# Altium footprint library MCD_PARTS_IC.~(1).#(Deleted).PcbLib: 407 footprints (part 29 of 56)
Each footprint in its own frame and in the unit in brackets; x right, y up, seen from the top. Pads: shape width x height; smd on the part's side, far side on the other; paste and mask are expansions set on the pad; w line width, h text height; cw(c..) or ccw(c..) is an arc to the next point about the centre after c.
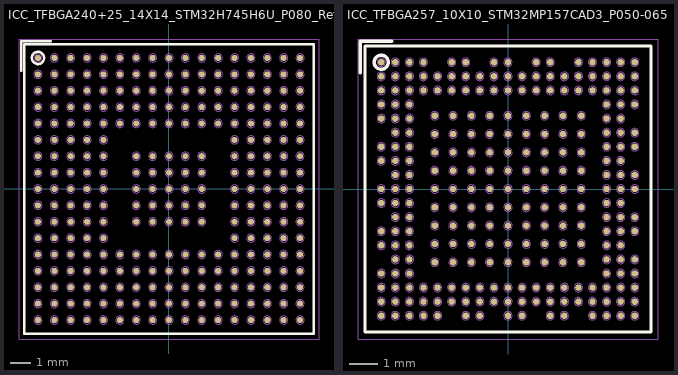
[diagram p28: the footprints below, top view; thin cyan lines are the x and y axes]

## ICC_TFBGA240+25_14X14_STM32H745H6U_P080_Ref2 [mm]
height 1.1
pads (265):
  round 0.3 smd mask+0.05: .U15(4.8,-6.4) A1(-6.4,6.4) A2(-5.6,6.4) A3(-4.8,6.4) A4(-4,6.4) A5(-3.2,6.4) A6(-2.4,6.4) A7(-1.6,6.4) A8(-0.8,6.4) A9(0,6.4) A10(0.8,6.4) A11(1.6,6.4) A12(2.4,6.4) A13(3.2,6.4) A14(4,6.4) A15(4.8,6.4) A16(5.6,6.4) A17(6.4,6.4) B1(-6.4,5.6) B2(-5.6,5.6) B3(-4.8,5.6) B4(-4,5.6) B5(-3.2,5.6) B6(-2.4,5.6) B7(-1.6,5.6) B8(-0.8,5.6) B9(0,5.6) B10(0.8,5.6) B11(1.6,5.6) B12(2.4,5.6) B13(3.2,5.6) B14(4,5.6) B15(4.8,5.6) B16(5.6,5.6) B17(6.4,5.6) C1(-6.4,4.8) C2(-5.6,4.8) C3(-4.8,4.8) C4(-4,4.8) C5(-3.2,4.8) C6(-2.4,4.8) C7(-1.6,4.8) C8(-0.8,4.8) C9(0,4.8) C10(0.8,4.8) C11(1.6,4.8) C12(2.4,4.8) C13(3.2,4.8) C14(4,4.8) C15(4.8,4.8) C16(5.6,4.8) C17(6.4,4.8) D1(-6.4,4) D2(-5.6,4) D3(-4.8,4) D4(-4,4) D5(-3.2,4) D6(-2.4,4) D7(-1.6,4) D8(-0.8,4) D9(0,4) D10(0.8,4) D11(1.6,4) D12(2.4,4) D13(3.2,4) D14(4,4) D15(4.8,4) D16(5.6,4) D17(6.4,4) E1(-6.4,3.2) E2(-5.6,3.2) E3(-4.8,3.2) E4(-4,3.2) E5(-3.2,3.2) E6(-2.4,3.2) E7(-1.6,3.2) E8(-0.8,3.2) E9(0,3.2) E10(0.8,3.2) E11(1.6,3.2) E12(2.4,3.2) E13(3.2,3.2) E14(4,3.2) E15(4.8,3.2) E16(5.6,3.2) E17(6.4,3.2) F1(-6.4,2.4) F2(-5.6,2.4) F3(-4.8,2.4) F4(-4,2.4) F5(-3.2,2.4) F13(3.2,2.4) F14(4,2.4) F15(4.8,2.4) F16(5.6,2.4) F17(6.4,2.4) G1(-6.4,1.6) G2(-5.6,1.6) G3(-4.8,1.6) G4(-4,1.6) G5(-3.2,1.6) G7(-1.6,1.6) G8(-0.8,1.6) G9(0,1.6) G10(0.8,1.6) G11(1.6,1.6) G13(3.2,1.6) G14(4,1.6) G15(4.8,1.6) G16(5.6,1.6) G17(6.4,1.6) H1(-6.4,0.8) H2(-5.6,0.8) H3(-4.8,0.8) H4(-4,0.8) H5(-3.2,0.8) H7(-1.6,0.8) H8(-0.8,0.8) H9(0,0.8) H10(0.8,0.8) H11(1.6,0.8) H13(3.2,0.8) H14(4,0.8) H15(4.8,0.8) H16(5.6,0.8) H17(6.4,0.8) J1(-6.4,0) J2(-5.6,0) J3(-4.8,0) J4(-4,0) J5(-3.2,0) J7(-1.6,0) J8(-0.8,0) J9(0,0) J10(0.8,0) J11(1.6,0) J13(3.2,0) J14(4,0) J15(4.8,0) J16(5.6,0) J17(6.4,0) K1(-6.4,-0.8) K2(-5.6,-0.8) K3(-4.8,-0.8) K4(-4,-0.8) K5(-3.2,-0.8) K7(-1.6,-0.8) K8(-0.8,-0.8) K9(0,-0.8) K10(0.8,-0.8) K11(1.6,-0.8) K13(3.2,-0.8) K14(4,-0.8) K15(4.8,-0.8) K16(5.6,-0.8) K17(6.4,-0.8) L1(-6.4,-1.6) L2(-5.6,-1.6) L3(-4.8,-1.6) L4(-4,-1.6) L5(-3.2,-1.6) L7(-1.6,-1.6) L8(-0.8,-1.6) L9(0,-1.6) L10(0.8,-1.6) L11(1.6,-1.6) L13(3.2,-1.6) L14(4,-1.6) L15(4.8,-1.6) L16(5.6,-1.6) L17(6.4,-1.6) M1(-6.4,-2.4) M2(-5.6,-2.4) M3(-4.8,-2.4) M4(-4,-2.4) M5(-3.2,-2.4) M13(3.2,-2.4) M14(4,-2.4) M15(4.8,-2.4) M16(5.6,-2.4) M17(6.4,-2.4) N1(-6.4,-3.2) N2(-5.6,-3.2) N3(-4.8,-3.2) N4(-4,-3.2) N5(-3.2,-3.2) N6(-2.4,-3.2) N7(-1.6,-3.2) N8(-0.8,-3.2) N9(0,-3.2) N10(0.8,-3.2) N11(1.6,-3.2) N12(2.4,-3.2) N13(3.2,-3.2) N14(4,-3.2) N15(4.8,-3.2) N16(5.6,-3.2) N17(6.4,-3.2) P1(-6.4,-4) P2(-5.6,-4) P3(-4.8,-4) P4(-4,-4) P5(-3.2,-4) P6(-2.4,-4) P7(-1.6,-4) P8(-0.8,-4) P9(0,-4) P10(0.8,-4) P11(1.6,-4) P12(2.4,-4) P13(3.2,-4) P14(4,-4) P15(4.8,-4) P16(5.6,-4) P17(6.4,-4) R1(-6.4,-4.8) R2(-5.6,-4.8) R3(-4.8,-4.8) R4(-4,-4.8) R5(-3.2,-4.8) R6(-2.4,-4.8) R7(-1.6,-4.8) R8(-0.8,-4.8) R9(0,-4.8) R10(0.8,-4.8) R11(1.6,-4.8) R12(2.4,-4.8) R13(3.2,-4.8) R14(4,-4.8) R15(4.8,-4.8) R16(5.6,-4.8) R17(6.4,-4.8) T1(-6.4,-5.6) T2(-5.6,-5.6) T3(-4.8,-5.6) T4(-4,-5.6) T5(-3.2,-5.6) T6(-2.4,-5.6) T7(-1.6,-5.6) T8(-0.8,-5.6) T9(0,-5.6) T10(0.8,-5.6) T11(1.6,-5.6) T12(2.4,-5.6) T13(3.2,-5.6) T14(4,-5.6) T15(4.8,-5.6) T16(5.6,-5.6) T17(6.4,-5.6) U1(-6.4,-6.4) U2(-5.6,-6.4) U3(-4.8,-6.4) U4(-4,-6.4) U5(-3.2,-6.4) U6(-2.4,-6.4) U7(-1.6,-6.4) U8(-0.8,-6.4) U9(0,-6.4) U10(0.8,-6.4) U11(1.6,-6.4) U12(2.4,-6.4) U13(3.2,-6.4) U14(4,-6.4) U16(5.6,-6.4) U17(6.4,-6.4)
Top Overlay:
  circle w0.12: c-6.4,6.4 r0.3
  lines w0.12: -7.225,5.775 -7.225,7.225 -5.775,7.225 ; -7.075,-7.075 -7.075,7.075 7.075,7.075 7.075,-7.075 -7.075,-7.075
M14-Top Assembly:
  drawing of 269 lines, arcs and shapes, not listed
  text "A1" at -6.65,6.225 h0.4
  text "'.Designator'" at -2,-0.5 h0.75
M16-Top Courtyard:
  lines w0.01: -7.325,-7.325 -7.325,7.325 7.325,7.325 7.325,-7.325 -7.325,-7.325
3D body: height 1.11, standoff 1.1, extent -6.698,6.101 -6.1,6.699
3D body: height 0.36, standoff -0.04, extent 4.601,-4.997 5,-4.603
3D body: height 0.36, standoff -0.04, extent 3.801,-4.997 4.2,-4.603
3D body: height 0.36, standoff -0.04, extent 3.001,-4.997 3.4,-4.603
3D body: height 0.36, standoff -0.04, extent 2.201,-4.997 2.6,-4.603
3D body: height 0.36, standoff -0.04, extent 1.401,-4.997 1.8,-4.603
3D body: height 0.36, standoff -0.04, extent -2.599,-4.997 -2.2,-4.603
3D body: height 0.36, standoff -0.04, extent -1.799,-4.997 -1.4,-4.603
3D body: height 0.36, standoff -0.04, extent -0.999,-4.997 -0.6,-4.603
3D body: height 0.36, standoff -0.04, extent -0.199,-4.997 0.2,-4.603
3D body: height 0.36, standoff -0.04, extent 0.601,-4.997 1,-4.603
3D body: height 0.36, standoff -0.04, extent -6.599,-4.997 -6.2,-4.603
3D body: height 0.36, standoff -0.04, extent -5.799,-4.997 -5.4,-4.603
3D body: height 0.36, standoff -0.04, extent -4.999,-4.997 -4.6,-4.603
3D body: height 0.36, standoff -0.04, extent -4.199,-4.997 -3.8,-4.603
3D body: height 0.36, standoff -0.04, extent -3.399,-4.997 -3,-4.603
3D body: height 0.36, standoff -0.04, extent 4.601,-4.197 5,-3.803
3D body: height 0.36, standoff -0.04, extent 3.801,-4.197 4.2,-3.803
3D body: height 0.36, standoff -0.04, extent 3.001,-4.197 3.4,-3.803
3D body: height 0.36, standoff -0.04, extent 2.201,-4.197 2.6,-3.803
3D body: height 0.36, standoff -0.04, extent 1.401,-4.197 1.8,-3.803
3D body: height 0.36, standoff -0.04, extent -2.599,-4.197 -2.2,-3.803
3D body: height 0.36, standoff -0.04, extent -1.799,-4.197 -1.4,-3.803
3D body: height 0.36, standoff -0.04, extent -0.999,-4.197 -0.6,-3.803
3D body: height 0.36, standoff -0.04, extent -0.199,-4.197 0.2,-3.803
3D body: height 0.36, standoff -0.04, extent 0.601,-4.197 1,-3.803
3D body: height 0.36, standoff -0.04, extent -6.599,-4.197 -6.2,-3.803
3D body: height 0.36, standoff -0.04, extent -5.799,-4.197 -5.4,-3.803
3D body: height 0.36, standoff -0.04, extent -4.999,-4.197 -4.6,-3.803
3D body: height 0.36, standoff -0.04, extent -4.199,-4.197 -3.8,-3.803
3D body: height 0.36, standoff -0.04, extent -3.399,-4.197 -3,-3.803
3D body: height 0.36, standoff -0.04, extent 4.601,-3.397 5,-3.003
3D body: height 0.36, standoff -0.04, extent 3.801,-3.397 4.2,-3.003
3D body: height 0.36, standoff -0.04, extent 3.001,-3.397 3.4,-3.003
3D body: height 0.36, standoff -0.04, extent 2.201,-3.397 2.6,-3.003
3D body: height 0.36, standoff -0.04, extent 1.401,-3.397 1.8,-3.003
3D body: height 0.36, standoff -0.04, extent -2.599,-3.397 -2.2,-3.003
3D body: height 0.36, standoff -0.04, extent -1.799,-3.397 -1.4,-3.003
3D body: height 0.36, standoff -0.04, extent -0.999,-3.397 -0.6,-3.003
3D body: height 0.36, standoff -0.04, extent -0.199,-3.397 0.2,-3.003
3D body: height 0.36, standoff -0.04, extent 0.601,-3.397 1,-3.003
3D body: height 0.36, standoff -0.04, extent -6.599,-3.397 -6.2,-3.003
3D body: height 0.36, standoff -0.04, extent -5.799,-3.397 -5.4,-3.003
3D body: height 0.36, standoff -0.04, extent -4.999,-3.397 -4.6,-3.003
3D body: height 0.36, standoff -0.04, extent -4.199,-3.397 -3.8,-3.003
3D body: height 0.36, standoff -0.04, extent -3.399,-3.397 -3,-3.003
3D body: height 0.36, standoff -0.04, extent 4.601,-2.597 5,-2.203
3D body: height 0.36, standoff -0.04, extent 3.801,-2.597 4.2,-2.203
3D body: height 0.36, standoff -0.04, extent 3.001,-2.597 3.4,-2.203
3D body: height 0.36, standoff -0.04, extent -6.599,-2.597 -6.2,-2.203
3D body: height 0.36, standoff -0.04, extent -5.799,-2.597 -5.4,-2.203
3D body: height 0.36, standoff -0.04, extent -4.999,-2.597 -4.6,-2.203
3D body: height 0.36, standoff -0.04, extent -4.199,-2.597 -3.8,-2.203
3D body: height 0.36, standoff -0.04, extent -3.399,-2.597 -3,-2.203
3D body: height 0.36, standoff -0.04, extent 4.601,-1.797 5,-1.403
3D body: height 0.36, standoff -0.04, extent 3.801,-1.797 4.2,-1.403
3D body: height 0.36, standoff -0.04, extent 3.001,-1.797 3.4,-1.403
3D body: height 0.36, standoff -0.04, extent 1.401,-1.797 1.8,-1.403
3D body: height 0.36, standoff -0.04, extent -1.799,-1.797 -1.4,-1.403
3D body: height 0.36, standoff -0.04, extent -0.999,-1.797 -0.6,-1.403
3D body: height 0.36, standoff -0.04, extent -0.199,-1.797 0.2,-1.403
3D body: height 0.36, standoff -0.04, extent 0.601,-1.797 1,-1.403
3D body: height 0.36, standoff -0.04, extent -6.599,-1.797 -6.2,-1.403
3D body: height 0.36, standoff -0.04, extent -5.799,-1.797 -5.4,-1.403
3D body: height 0.36, standoff -0.04, extent -4.999,-1.797 -4.6,-1.403
3D body: height 0.36, standoff -0.04, extent -4.199,-1.797 -3.8,-1.403
3D body: height 0.36, standoff -0.04, extent -3.399,-1.797 -3,-1.403
3D body: height 0.36, standoff -0.04, extent 4.601,-0.997 5,-0.603
3D body: height 0.36, standoff -0.04, extent 3.801,-0.997 4.2,-0.603
3D body: height 0.36, standoff -0.04, extent 3.001,-0.997 3.4,-0.603
3D body: height 0.36, standoff -0.04, extent 1.401,-0.997 1.8,-0.603
3D body: height 0.36, standoff -0.04, extent -1.799,-0.997 -1.4,-0.603
3D body: height 0.36, standoff -0.04, extent -0.999,-0.997 -0.6,-0.603
3D body: height 0.36, standoff -0.04, extent -0.199,-0.997 0.2,-0.603
3D body: height 0.36, standoff -0.04, extent 0.601,-0.997 1,-0.603
3D body: height 0.36, standoff -0.04, extent -6.599,-0.997 -6.2,-0.603
3D body: height 0.36, standoff -0.04, extent -5.799,-0.997 -5.4,-0.603
3D body: height 0.36, standoff -0.04, extent -4.999,-0.997 -4.6,-0.603
3D body: height 0.36, standoff -0.04, extent -4.199,-0.997 -3.8,-0.603
3D body: height 0.36, standoff -0.04, extent -3.399,-0.997 -3,-0.603
3D body: height 0.36, standoff -0.04, extent 4.601,-0.197 5,0.197
3D body: height 0.36, standoff -0.04, extent 3.801,-0.197 4.2,0.197
3D body: height 0.36, standoff -0.04, extent 3.001,-0.197 3.4,0.197
3D body: height 0.36, standoff -0.04, extent 1.401,-0.197 1.8,0.197
3D body: height 0.36, standoff -0.04, extent -1.799,-0.197 -1.4,0.197
3D body: height 0.36, standoff -0.04, extent -0.999,-0.197 -0.6,0.197
3D body: height 0.36, standoff -0.04, extent -0.199,-0.197 0.2,0.197
3D body: height 0.36, standoff -0.04, extent 0.601,-0.197 1,0.197
3D body: height 0.36, standoff -0.04, extent -6.599,-0.197 -6.2,0.197
3D body: height 0.36, standoff -0.04, extent -5.799,-0.197 -5.4,0.197
3D body: height 0.36, standoff -0.04, extent -4.999,-0.197 -4.6,0.197
3D body: height 0.36, standoff -0.04, extent -4.199,-0.197 -3.8,0.197
3D body: height 0.36, standoff -0.04, extent -3.399,-0.197 -3,0.197
3D body: height 0.36, standoff -0.04, extent 4.601,0.603 5,0.997
3D body: height 0.36, standoff -0.04, extent 3.801,0.603 4.2,0.997
3D body: height 0.36, standoff -0.04, extent 3.001,0.603 3.4,0.997
3D body: height 0.36, standoff -0.04, extent 1.401,0.603 1.8,0.997
3D body: height 0.36, standoff -0.04, extent -1.799,0.603 -1.4,0.997
3D body: height 0.36, standoff -0.04, extent -0.999,0.603 -0.6,0.997
3D body: height 0.36, standoff -0.04, extent -0.199,0.603 0.2,0.997
3D body: height 0.36, standoff -0.04, extent 0.601,0.603 1,0.997
3D body: height 0.36, standoff -0.04, extent -6.599,0.603 -6.2,0.997
3D body: height 0.36, standoff -0.04, extent -5.799,0.603 -5.4,0.997
3D body: height 0.36, standoff -0.04, extent -4.999,0.603 -4.6,0.997
3D body: height 0.36, standoff -0.04, extent -4.199,0.603 -3.8,0.997
3D body: height 0.36, standoff -0.04, extent -3.399,0.603 -3,0.997
3D body: height 0.36, standoff -0.04, extent 4.601,1.403 5,1.797
3D body: height 0.36, standoff -0.04, extent 3.801,1.403 4.2,1.797
3D body: height 0.36, standoff -0.04, extent 3.001,1.403 3.4,1.797
3D body: height 0.36, standoff -0.04, extent 1.401,1.403 1.8,1.797
3D body: height 0.36, standoff -0.04, extent -1.799,1.403 -1.4,1.797
3D body: height 0.36, standoff -0.04, extent -0.999,1.403 -0.6,1.797
3D body: height 0.36, standoff -0.04, extent -0.199,1.403 0.2,1.797
3D body: height 0.36, standoff -0.04, extent 0.601,1.403 1,1.797
3D body: height 0.36, standoff -0.04, extent -6.599,1.403 -6.2,1.797
3D body: height 0.36, standoff -0.04, extent -5.799,1.403 -5.4,1.797
3D body: height 0.36, standoff -0.04, extent -4.999,1.403 -4.6,1.797
3D body: height 0.36, standoff -0.04, extent -4.199,1.403 -3.8,1.797
3D body: height 0.36, standoff -0.04, extent -3.399,1.403 -3,1.797
3D body: height 0.36, standoff -0.04, extent 4.601,2.203 5,2.597
3D body: height 0.36, standoff -0.04, extent 3.801,2.203 4.2,2.597
3D body: height 0.36, standoff -0.04, extent 3.001,2.203 3.4,2.597
3D body: height 0.36, standoff -0.04, extent -6.599,2.203 -6.2,2.597
3D body: height 0.36, standoff -0.04, extent -5.799,2.203 -5.4,2.597
3D body: height 0.36, standoff -0.04, extent -4.999,2.203 -4.6,2.597
3D body: height 0.36, standoff -0.04, extent -4.199,2.203 -3.8,2.597
3D body: height 0.36, standoff -0.04, extent -3.399,2.203 -3,2.597
3D body: height 0.36, standoff -0.04, extent 4.601,3.003 5,3.397
3D body: height 0.36, standoff -0.04, extent 3.801,3.003 4.2,3.397
3D body: height 0.36, standoff -0.04, extent 3.001,3.003 3.4,3.397
3D body: height 0.36, standoff -0.04, extent 2.201,3.003 2.6,3.397
3D body: height 0.36, standoff -0.04, extent 1.401,3.003 1.8,3.397
3D body: height 0.36, standoff -0.04, extent -2.599,3.003 -2.2,3.397
3D body: height 0.36, standoff -0.04, extent -1.799,3.003 -1.4,3.397
3D body: height 0.36, standoff -0.04, extent -0.999,3.003 -0.6,3.397
3D body: height 0.36, standoff -0.04, extent -0.199,3.003 0.2,3.397
3D body: height 0.36, standoff -0.04, extent 0.601,3.003 1,3.397
3D body: height 0.36, standoff -0.04, extent -6.599,3.003 -6.2,3.397
3D body: height 0.36, standoff -0.04, extent -5.799,3.003 -5.4,3.397
3D body: height 0.36, standoff -0.04, extent -4.999,3.003 -4.6,3.397
3D body: height 0.36, standoff -0.04, extent -4.199,3.003 -3.8,3.397
3D body: height 0.36, standoff -0.04, extent -3.399,3.003 -3,3.397
3D body: height 0.36, standoff -0.04, extent 4.601,3.803 5,4.197
3D body: height 0.36, standoff -0.04, extent 3.801,3.803 4.2,4.197
3D body: height 0.36, standoff -0.04, extent 3.001,3.803 3.4,4.197
3D body: height 0.36, standoff -0.04, extent 2.201,3.803 2.6,4.197
3D body: height 0.36, standoff -0.04, extent 1.401,3.803 1.8,4.197
3D body: height 0.36, standoff -0.04, extent -2.599,3.803 -2.2,4.197
3D body: height 0.36, standoff -0.04, extent -1.799,3.803 -1.4,4.197
3D body: height 0.36, standoff -0.04, extent -0.999,3.803 -0.6,4.197
3D body: height 0.36, standoff -0.04, extent -0.199,3.803 0.2,4.197
3D body: height 0.36, standoff -0.04, extent 0.601,3.803 1,4.197
3D body: height 0.36, standoff -0.04, extent -6.599,3.803 -6.2,4.197
3D body: height 0.36, standoff -0.04, extent -5.799,3.803 -5.4,4.197
3D body: height 0.36, standoff -0.04, extent -4.999,3.803 -4.6,4.197
3D body: height 0.36, standoff -0.04, extent -4.199,3.803 -3.8,4.197
3D body: height 0.36, standoff -0.04, extent -3.399,3.803 -3,4.197
3D body: height 0.36, standoff -0.04, extent 4.601,4.603 5,4.997
3D body: height 0.36, standoff -0.04, extent 3.801,4.603 4.2,4.997
3D body: height 0.36, standoff -0.04, extent 3.001,4.603 3.4,4.997
3D body: height 0.36, standoff -0.04, extent 2.201,4.603 2.6,4.997
3D body: height 0.36, standoff -0.04, extent 1.401,4.603 1.8,4.997
3D body: height 0.36, standoff -0.04, extent -2.599,4.603 -2.2,4.997
3D body: height 0.36, standoff -0.04, extent -1.799,4.603 -1.4,4.997
3D body: height 0.36, standoff -0.04, extent -0.999,4.603 -0.6,4.997
3D body: height 0.36, standoff -0.04, extent -0.199,4.603 0.2,4.997
3D body: height 0.36, standoff -0.04, extent 0.601,4.603 1,4.997
3D body: height 0.36, standoff -0.04, extent -6.599,4.603 -6.2,4.997
3D body: height 0.36, standoff -0.04, extent -5.799,4.603 -5.4,4.997
3D body: height 0.36, standoff -0.04, extent -4.999,4.603 -4.6,4.997
3D body: height 0.36, standoff -0.04, extent -4.199,4.603 -3.8,4.997
3D body: height 0.36, standoff -0.04, extent -3.399,4.603 -3,4.997
3D body: height 0.36, standoff -0.04, extent 4.601,5.403 5,5.797
3D body: height 0.36, standoff -0.04, extent 3.801,5.403 4.2,5.797
3D body: height 0.36, standoff -0.04, extent 3.001,5.403 3.4,5.797
3D body: height 0.36, standoff -0.04, extent 2.201,5.403 2.6,5.797
3D body: height 0.36, standoff -0.04, extent 1.401,5.403 1.8,5.797
3D body: height 0.36, standoff -0.04, extent -2.599,5.403 -2.2,5.797
3D body: height 0.36, standoff -0.04, extent -1.799,5.403 -1.4,5.797
3D body: height 0.36, standoff -0.04, extent -0.999,5.403 -0.6,5.797
3D body: height 0.36, standoff -0.04, extent -0.199,5.403 0.2,5.797
3D body: height 0.36, standoff -0.04, extent 0.601,5.403 1,5.797
3D body: height 0.36, standoff -0.04, extent -6.599,5.403 -6.2,5.797
3D body: height 0.36, standoff -0.04, extent -5.799,5.403 -5.4,5.797
3D body: height 0.36, standoff -0.04, extent -4.999,5.403 -4.6,5.797
3D body: height 0.36, standoff -0.04, extent -4.199,5.403 -3.8,5.797
3D body: height 0.36, standoff -0.04, extent -3.399,5.403 -3,5.797
3D body: height 0.36, standoff -0.04, extent -3.399,6.203 -3,6.597
3D body: height 0.36, standoff -0.04, extent -4.199,6.203 -3.8,6.597
3D body: height 0.36, standoff -0.04, extent -4.999,6.203 -4.6,6.597
3D body: height 0.36, standoff -0.04, extent -5.799,6.203 -5.4,6.597
3D body: height 0.36, standoff -0.04, extent -6.599,6.203 -6.2,6.597
3D body: height 0.36, standoff -0.04, extent 0.601,6.203 1,6.597
3D body: height 0.36, standoff -0.04, extent -0.199,6.203 0.2,6.597
3D body: height 0.36, standoff -0.04, extent -0.999,6.203 -0.6,6.597
3D body: height 0.36, standoff -0.04, extent -1.799,6.203 -1.4,6.597
3D body: height 0.36, standoff -0.04, extent -2.599,6.203 -2.2,6.597
3D body: height 0.36, standoff -0.04, extent 1.401,6.203 1.8,6.597
3D body: height 0.36, standoff -0.04, extent 2.201,6.203 2.6,6.597
3D body: height 0.36, standoff -0.04, extent 3.001,6.203 3.4,6.597
3D body: height 0.36, standoff -0.04, extent 3.801,6.203 4.2,6.597
3D body: height 1.1, standoff 0.3, extent -7.075,-7.075 7.075,7.075
3D body: height 0.36, standoff -0.04, extent 4.601,6.203 5,6.597
3D body: height 0.36, standoff -0.04, extent 6.201,6.203 6.6,6.597
3D body: height 0.36, standoff -0.04, extent 5.401,6.203 5.8,6.597
3D body: height 0.36, standoff -0.04, extent 5.401,5.403 5.8,5.797
3D body: height 0.36, standoff -0.04, extent 6.201,5.403 6.6,5.797
3D body: height 0.36, standoff -0.04, extent 5.401,4.603 5.8,4.997
3D body: height 0.36, standoff -0.04, extent 6.201,4.603 6.6,4.997
3D body: height 0.36, standoff -0.04, extent 5.401,3.803 5.8,4.197
3D body: height 0.36, standoff -0.04, extent 6.201,3.803 6.6,4.197
3D body: height 0.36, standoff -0.04, extent 5.401,3.003 5.8,3.397
3D body: height 0.36, standoff -0.04, extent 6.201,3.003 6.6,3.397
3D body: height 0.36, standoff -0.04, extent 5.401,2.203 5.8,2.597
3D body: height 0.36, standoff -0.04, extent 6.201,2.203 6.6,2.597
3D body: height 0.36, standoff -0.04, extent 5.401,1.403 5.8,1.797
3D body: height 0.36, standoff -0.04, extent 6.201,1.403 6.6,1.797
3D body: height 0.36, standoff -0.04, extent 5.401,0.603 5.8,0.997
3D body: height 0.36, standoff -0.04, extent 6.201,0.603 6.6,0.997
3D body: height 0.36, standoff -0.04, extent 5.401,-0.197 5.8,0.197
3D body: height 0.36, standoff -0.04, extent 6.201,-0.197 6.6,0.197
3D body: height 0.36, standoff -0.04, extent 5.401,-0.997 5.8,-0.603
3D body: height 0.36, standoff -0.04, extent 6.201,-0.997 6.6,-0.603
3D body: height 0.36, standoff -0.04, extent 5.401,-1.797 5.8,-1.403
3D body: height 0.36, standoff -0.04, extent 6.201,-1.797 6.6,-1.403
3D body: height 0.36, standoff -0.04, extent 5.401,-2.597 5.8,-2.203
3D body: height 0.36, standoff -0.04, extent 6.201,-2.597 6.6,-2.203
3D body: height 0.36, standoff -0.04, extent 5.401,-3.397 5.8,-3.003
3D body: height 0.36, standoff -0.04, extent 6.201,-3.397 6.6,-3.003
3D body: height 0.36, standoff -0.04, extent 5.401,-4.197 5.8,-3.803
3D body: height 0.36, standoff -0.04, extent 6.201,-4.197 6.6,-3.803
3D body: height 0.36, standoff -0.04, extent 5.401,-4.997 5.8,-4.603
3D body: height 0.36, standoff -0.04, extent 6.201,-4.997 6.6,-4.603
3D body: height 0.36, standoff -0.04, extent 6.201,-6.597 6.6,-6.203
3D body: height 0.36, standoff -0.04, extent 5.401,-6.597 5.8,-6.203
3D body: height 0.36, standoff -0.04, extent 6.201,-5.797 6.6,-5.403
3D body: height 0.36, standoff -0.04, extent 5.401,-5.797 5.8,-5.403
3D body: height 0.36, standoff -0.04, extent -3.399,-5.797 -3,-5.403
3D body: height 0.36, standoff -0.04, extent -4.199,-5.797 -3.8,-5.403
3D body: height 0.36, standoff -0.04, extent -4.999,-5.797 -4.6,-5.403
3D body: height 0.36, standoff -0.04, extent -5.799,-5.797 -5.4,-5.403
3D body: height 0.36, standoff -0.04, extent -6.599,-5.797 -6.2,-5.403
3D body: height 0.36, standoff -0.04, extent 0.601,-5.797 1,-5.403
3D body: height 0.36, standoff -0.04, extent -0.199,-5.797 0.2,-5.403
3D body: height 0.36, standoff -0.04, extent -0.999,-5.797 -0.6,-5.403
3D body: height 0.36, standoff -0.04, extent -1.799,-5.797 -1.4,-5.403
3D body: height 0.36, standoff -0.04, extent -2.599,-5.797 -2.2,-5.403
3D body: height 0.36, standoff -0.04, extent 1.401,-5.797 1.8,-5.403
3D body: height 0.36, standoff -0.04, extent 2.201,-5.797 2.6,-5.403
3D body: height 0.36, standoff -0.04, extent 3.001,-5.797 3.4,-5.403
3D body: height 0.36, standoff -0.04, extent 3.801,-5.797 4.2,-5.403
3D body: height 0.36, standoff -0.04, extent 4.601,-5.797 5,-5.403
3D body: height 0.36, standoff -0.04, extent -3.399,-6.597 -3,-6.203
3D body: height 0.36, standoff -0.04, extent -4.199,-6.597 -3.8,-6.203
3D body: height 0.36, standoff -0.04, extent -4.999,-6.597 -4.6,-6.203
3D body: height 0.36, standoff -0.04, extent -5.799,-6.597 -5.4,-6.203
3D body: height 0.36, standoff -0.04, extent -6.599,-6.597 -6.2,-6.203
3D body: height 0.36, standoff -0.04, extent 0.601,-6.597 1,-6.203
3D body: height 0.36, standoff -0.04, extent -0.199,-6.597 0.2,-6.203
3D body: height 0.36, standoff -0.04, extent -0.999,-6.597 -0.6,-6.203
3D body: height 0.36, standoff -0.04, extent -1.799,-6.597 -1.4,-6.203
3D body: height 0.36, standoff -0.04, extent -2.599,-6.597 -2.2,-6.203
3D body: height 0.36, standoff -0.04, extent 1.401,-6.597 1.8,-6.203
3D body: height 0.36, standoff -0.04, extent 2.201,-6.597 2.6,-6.203
3D body: height 0.36, standoff -0.04, extent 3.001,-6.597 3.4,-6.203
3D body: height 0.36, standoff -0.04, extent 3.801,-6.597 4.2,-6.203
3D body: height 0.36, standoff -0.04, extent 4.601,-6.597 5,-6.203

## ICC_TFBGA257_10X10_STM32MP157CAD3_P050-065 [mm] "MCD-01144"
height 1.2
pads (257):
  round 0.23 smd paste+0.025 mask+0.05: 1A1(-2.6,2.6) 1A2(-1.95,2.6) 1A3(-1.3,2.6) 1A4(-0.65,2.6) 1A5(0,2.6) 1A6(0.65,2.6) 1A7(1.3,2.6) 1A8(1.95,2.6) 1A9(2.6,2.6) 1B1(-2.6,1.95) 1B2(-1.95,1.95) 1B3(-1.3,1.95) 1B4(-0.65,1.95) 1B5(0,1.95) 1B6(0.65,1.95) 1B7(1.3,1.95) 1B8(1.95,1.95) 1B9(2.6,1.95) 1C1(-2.6,1.3) 1C2(-1.95,1.3) 1C3(-1.3,1.3) 1C4(-0.65,1.3) 1C5(0,1.3) 1C6(0.65,1.3) 1C7(1.3,1.3) 1C8(1.95,1.3) 1C9(2.6,1.3) 1D1(-2.6,0.65) 1D2(-1.95,0.65) 1D3(-1.3,0.65) 1D4(-0.65,0.65) 1D5(0,0.65) 1D6(0.65,0.65) 1D7(1.3,0.65) 1D8(1.95,0.65) 1D9(2.6,0.65) 1E1(-2.6,0) 1E2(-1.95,0) 1E3(-1.3,0) 1E4(-0.65,0) 1E5(0,0) 1E6(0.65,0) 1E7(1.3,0) 1E8(1.95,0) 1E9(2.6,0) 1F1(-2.6,-0.65) 1F2(-1.95,-0.65) 1F3(-1.3,-0.65) 1F4(-0.65,-0.65) 1F5(0,-0.65) 1F6(0.65,-0.65) 1F7(1.3,-0.65) 1F8(1.95,-0.65) 1F9(2.6,-0.65) 1G1(-2.6,-1.3) 1G2(-1.95,-1.3) 1G3(-1.3,-1.3) 1G4(-0.65,-1.3) 1G5(0,-1.3) 1G6(0.65,-1.3) 1G7(1.3,-1.3) 1G8(1.95,-1.3) 1G9(2.6,-1.3) 1H1(-2.6,-1.95) 1H2(-1.95,-1.95) 1H3(-1.3,-1.95) 1H4(-0.65,-1.95) 1H5(0,-1.95) 1H6(0.65,-1.95) 1H7(1.3,-1.95) 1H8(1.95,-1.95) 1H9(2.6,-1.95) 1J1(-2.6,-2.6) 1J2(-1.95,-2.6) 1J3(-1.3,-2.6) 1J4(-0.65,-2.6) 1J5(0,-2.6) 1J6(0.65,-2.6) 1J7(1.3,-2.6) 1J8(1.95,-2.6) 1J9(2.6,-2.6) A1(-4.5,4.5) A2(-4,4.5) A3(-3.5,4.5) A4(-3,4.5) A6(-2,4.5) A7(-1.5,4.5) A9(-0.5,4.5) A10(0,4.5) A12(1,4.5) A13(1.5,4.5) A15(2.5,4.5) A16(3,4.5) A17(3.5,4.5) A18(4,4.5) A19(4.5,4.5) B1(-4.5,4) B2(-4,4) B3(-3.5,4) B4(-3,4) B5(-2.5,4) B6(-2,4) B7(-1.5,4) B8(-1,4) B9(-0.5,4) B10(0,4) B11(0.5,4) B12(1,4) B13(1.5,4) B14(2,4) B15(2.5,4) B16(3,4) B17(3.5,4) B18(4,4) B19(4.5,4) C1(-4.5,3.5) C2(-4,3.5) C3(-3.5,3.5) C4(-3,3.5) C5(-2.5,3.5) C6(-2,3.5) C7(-1.5,3.5) C8(-1,3.5) C9(-0.5,3.5) C10(0,3.5) C11(0.5,3.5) C12(1,3.5) C13(1.5,3.5) C14(2,3.5) C15(2.5,3.5) C16(3,3.5) C17(3.5,3.5) C18(4,3.5) C19(4.5,3.5) D1(-4.5,3) D2(-4,3) D3(-3.5,3) D17(3.5,3) D18(4,3) D19(4.5,3) E1(-4.5,2.5) E2(-4,2.5) E3(-3.5,2.5) E17(3.5,2.5) E18(4,2.5) F2(-4,2) F3(-3.5,2) F17(3.5,2) F18(4,2) F19(4.5,2) G1(-4.5,1.5) G2(-4,1.5) G3(-3.5,1.5) G17(3.5,1.5) G18(4,1.5) G19(4.5,1.5) H1(-4.5,1) H2(-4,1) H3(-3.5,1) H17(3.5,1) H18(4,1) J2(-4,0.5) J3(-3.5,0.5) J17(3.5,0.5) J18(4,0.5) J19(4.5,0.5) K1(-4.5,0) K2(-4,0) K3(-3.5,0) K17(3.5,0) K18(4,0) K19(4.5,0) L1(-4.5,-0.5) L2(-4,-0.5) L3(-3.5,-0.5) L17(3.5,-0.5) L18(4,-0.5) M2(-4,-1) M3(-3.5,-1) M17(3.5,-1) M18(4,-1) M19(4.5,-1) N1(-4.5,-1.5) N2(-4,-1.5) N3(-3.5,-1.5) N17(3.5,-1.5) N18(4,-1.5) N19(4.5,-1.5) P1(-4.5,-2) P2(-4,-2) P3(-3.5,-2) P17(3.5,-2) P18(4,-2) R2(-4,-2.5) R3(-3.5,-2.5) R17(3.5,-2.5) R18(4,-2.5) R19(4.5,-2.5) T1(-4.5,-3) T2(-4,-3) T3(-3.5,-3) T17(3.5,-3) T18(4,-3) T19(4.5,-3) U1(-4.5,-3.5) U2(-4,-3.5) U3(-3.5,-3.5) U4(-3,-3.5) U5(-2.5,-3.5) U6(-2,-3.5) U7(-1.5,-3.5) U8(-1,-3.5) U9(-0.5,-3.5) U10(0,-3.5) U11(0.5,-3.5) U12(1,-3.5) U13(1.5,-3.5) U14(2,-3.5) U15(2.5,-3.5) U16(3,-3.5) U17(3.5,-3.5) U18(4,-3.5) U19(4.5,-3.5) V1(-4.5,-4) V2(-4,-4) V3(-3.5,-4) V4(-3,-4) V5(-2.5,-4) V6(-2,-4) V7(-1.5,-4) V8(-1,-4) V9(-0.5,-4) V10(0,-4) V11(0.5,-4) V12(1,-4) V13(1.5,-4) V14(2,-4) V15(2.5,-4) V16(3,-4) V17(3.5,-4) V18(4,-4) V19(4.5,-4) W1(-4.5,-4.5) W2(-4,-4.5) W3(-3.5,-4.5) W4(-3,-4.5) W5(-2.5,-4.5) W7(-1.5,-4.5) W8(-1,-4.5) W10(0,-4.5) W11(0.5,-4.5) W13(1.5,-4.5) W14(2,-4.5) W16(3,-4.5) W17(3.5,-4.5) W18(4,-4.5) W19(4.5,-4.5)
Top Overlay:
  circle w0.12: c-4.5,4.5 r0.251
  lines w0.12: -5.25,4.125 -5.25,5.25 -4.125,5.25 ; -5.075,-5.075 -5.075,5.075 5.075,5.075 5.075,-5.075 -5.075,-5.075
M14-Top Assembly:
  drawing of 261 lines, arcs and shapes, not listed
  text "1A1" at -2.95,2.45 h0.5
  text "A1" at -4.775,4.35 h0.5
  text "'.Designator'" at -2,-0.5 h0.75
M16-Top Courtyard:
  lines w0.01: -5.325,-5.325 5.325,-5.325 5.325,5.325 -5.325,5.325 -5.325,-5.325
3D body: height 0.26, standoff -0.04, extent -2.748,-2.741 -2.452,-2.45
3D body: height 0.26, standoff -0.04, extent -2.098,-2.741 -1.802,-2.45
3D body: height 0.26, standoff -0.04, extent -1.448,-2.741 -1.152,-2.45
3D body: height 0.26, standoff -0.04, extent -0.798,-2.741 -0.502,-2.45
3D body: height 0.26, standoff -0.04, extent -0.148,-2.741 0.148,-2.45
3D body: height 0.26, standoff -0.04, extent 0.502,-2.741 0.798,-2.45
3D body: height 0.26, standoff -0.04, extent 1.152,-2.741 1.448,-2.45
3D body: height 0.26, standoff -0.04, extent 1.802,-2.741 2.098,-2.45
3D body: height 0.26, standoff -0.04, extent 2.452,-2.741 2.748,-2.45
3D body: height 0.26, standoff -0.04, extent -2.748,-2.091 -2.452,-1.8
3D body: height 0.26, standoff -0.04, extent -2.098,-2.091 -1.802,-1.8
3D body: height 0.26, standoff -0.04, extent -1.448,-2.091 -1.152,-1.8
3D body: height 0.26, standoff -0.04, extent -0.798,-2.091 -0.502,-1.8
3D body: height 0.26, standoff -0.04, extent -0.148,-2.091 0.148,-1.8
3D body: height 0.26, standoff -0.04, extent 0.502,-2.091 0.798,-1.8
3D body: height 0.26, standoff -0.04, extent 1.152,-2.091 1.448,-1.8
3D body: height 0.26, standoff -0.04, extent 1.802,-2.091 2.098,-1.8
3D body: height 0.26, standoff -0.04, extent 2.452,-2.091 2.748,-1.8
3D body: height 0.26, standoff -0.04, extent -2.748,-1.441 -2.452,-1.15
3D body: height 0.26, standoff -0.04, extent -2.098,-1.441 -1.802,-1.15
3D body: height 0.26, standoff -0.04, extent -1.448,-1.441 -1.152,-1.15
3D body: height 0.26, standoff -0.04, extent -0.798,-1.441 -0.502,-1.15
3D body: height 0.26, standoff -0.04, extent -0.148,-1.441 0.148,-1.15
3D body: height 0.26, standoff -0.04, extent 0.502,-1.441 0.798,-1.15
3D body: height 0.26, standoff -0.04, extent 1.152,-1.441 1.448,-1.15
3D body: height 0.26, standoff -0.04, extent 1.802,-1.441 2.098,-1.15
3D body: height 0.26, standoff -0.04, extent 2.452,-1.441 2.748,-1.15
3D body: height 0.26, standoff -0.04, extent -2.748,-0.791 -2.452,-0.5
3D body: height 0.26, standoff -0.04, extent -2.098,-0.791 -1.802,-0.5
3D body: height 0.26, standoff -0.04, extent -1.448,-0.791 -1.152,-0.5
3D body: height 0.26, standoff -0.04, extent -0.798,-0.791 -0.502,-0.5
3D body: height 0.26, standoff -0.04, extent -0.148,-0.791 0.148,-0.5
3D body: height 0.26, standoff -0.04, extent 0.502,-0.791 0.798,-0.5
3D body: height 0.26, standoff -0.04, extent 1.152,-0.791 1.448,-0.5
3D body: height 0.26, standoff -0.04, extent 1.802,-0.791 2.098,-0.5
3D body: height 0.26, standoff -0.04, extent 2.452,-0.791 2.748,-0.5
3D body: height 0.26, standoff -0.04, extent -2.748,-0.141 -2.452,0.15
3D body: height 0.26, standoff -0.04, extent -2.098,-0.141 -1.802,0.15
3D body: height 0.26, standoff -0.04, extent -1.448,-0.141 -1.152,0.15
3D body: height 0.26, standoff -0.04, extent -0.798,-0.141 -0.502,0.15
3D body: height 0.26, standoff -0.04, extent -0.148,-0.141 0.148,0.15
3D body: height 0.26, standoff -0.04, extent 0.502,-0.141 0.798,0.15
3D body: height 0.26, standoff -0.04, extent 1.152,-0.141 1.448,0.15
3D body: height 0.26, standoff -0.04, extent 1.802,-0.141 2.098,0.15
3D body: height 0.26, standoff -0.04, extent 2.452,-0.141 2.748,0.15
3D body: height 0.26, standoff -0.04, extent -2.748,0.509 -2.452,0.8
3D body: height 0.26, standoff -0.04, extent -2.098,0.509 -1.802,0.8
3D body: height 0.26, standoff -0.04, extent -1.448,0.509 -1.152,0.8
3D body: height 0.26, standoff -0.04, extent -0.798,0.509 -0.502,0.8
3D body: height 0.26, standoff -0.04, extent -0.148,0.509 0.148,0.8
3D body: height 0.26, standoff -0.04, extent 0.502,0.509 0.798,0.8
3D body: height 0.26, standoff -0.04, extent 1.152,0.509 1.448,0.8
3D body: height 0.26, standoff -0.04, extent 1.802,0.509 2.098,0.8
3D body: height 0.26, standoff -0.04, extent 2.452,0.509 2.748,0.8
3D body: height 0.26, standoff -0.04, extent -2.748,1.159 -2.452,1.45
3D body: height 0.26, standoff -0.04, extent -2.098,1.159 -1.802,1.45
3D body: height 0.26, standoff -0.04, extent -1.448,1.159 -1.152,1.45
3D body: height 0.26, standoff -0.04, extent -0.798,1.159 -0.502,1.45
3D body: height 0.26, standoff -0.04, extent -0.148,1.159 0.148,1.45
3D body: height 0.26, standoff -0.04, extent 0.502,1.159 0.798,1.45
3D body: height 0.26, standoff -0.04, extent 1.152,1.159 1.448,1.45
3D body: height 0.26, standoff -0.04, extent 1.802,1.159 2.098,1.45
3D body: height 0.26, standoff -0.04, extent 2.452,1.159 2.748,1.45
3D body: height 0.26, standoff -0.04, extent -2.748,1.809 -2.452,2.1
3D body: height 0.26, standoff -0.04, extent -2.098,1.809 -1.802,2.1
3D body: height 0.26, standoff -0.04, extent -1.448,1.809 -1.152,2.1
3D body: height 0.26, standoff -0.04, extent -0.798,1.809 -0.502,2.1
3D body: height 0.26, standoff -0.04, extent -0.148,1.809 0.148,2.1
3D body: height 0.26, standoff -0.04, extent 0.502,1.809 0.798,2.1
3D body: height 0.26, standoff -0.04, extent 1.152,1.809 1.448,2.1
3D body: height 0.26, standoff -0.04, extent 1.802,1.809 2.098,2.1
3D body: height 0.26, standoff -0.04, extent 2.452,1.809 2.748,2.1
3D body: height 0.26, standoff -0.04, extent 2.452,2.459 2.748,2.75
3D body: height 0.26, standoff -0.04, extent 1.802,2.459 2.098,2.75
3D body: height 0.26, standoff -0.04, extent 1.152,2.459 1.448,2.75
3D body: height 0.26, standoff -0.04, extent 0.502,2.459 0.798,2.75
3D body: height 0.26, standoff -0.04, extent -0.148,2.459 0.148,2.75
3D body: height 0.26, standoff -0.04, extent -0.798,2.459 -0.502,2.75
3D body: height 0.26, standoff -0.04, extent -1.448,2.459 -1.152,2.75
3D body: height 0.26, standoff -0.04, extent -2.098,2.459 -1.802,2.75
3D body: height 0.26, standoff -0.04, extent -2.748,2.459 -2.452,2.75
3D body: height 0.26, standoff -0.04, extent -3.141,-4.647 -2.85,-4.352
3D body: height 0.26, standoff -0.04, extent -2.641,-4.647 -2.35,-4.352
3D body: height 0.26, standoff -0.04, extent -1.641,-4.647 -1.35,-4.352
3D body: height 0.26, standoff -0.04, extent -1.141,-4.647 -0.85,-4.352
3D body: height 0.26, standoff -0.04, extent -0.141,-4.647 0.15,-4.352
3D body: height 0.26, standoff -0.04, extent 0.359,-4.647 0.65,-4.352
3D body: height 0.26, standoff -0.04, extent 1.359,-4.647 1.65,-4.352
3D body: height 0.26, standoff -0.04, extent 1.859,-4.647 2.15,-4.352
3D body: height 0.26, standoff -0.04, extent 2.859,-4.647 3.15,-4.352
3D body: height 0.26, standoff -0.04, extent 3.359,-4.647 3.65,-4.352
3D body: height 0.26, standoff -0.04, extent 3.859,-4.647 4.15,-4.352
3D body: height 0.26, standoff -0.04, extent 4.359,-4.647 4.65,-4.352
3D body: height 0.26, standoff -0.04, extent -3.141,-4.147 -2.85,-3.852
3D body: height 0.26, standoff -0.04, extent -2.641,-4.147 -2.35,-3.852
3D body: height 0.26, standoff -0.04, extent -2.141,-4.147 -1.85,-3.852
3D body: height 0.26, standoff -0.04, extent -1.641,-4.147 -1.35,-3.852
3D body: height 0.26, standoff -0.04, extent -1.141,-4.147 -0.85,-3.852
3D body: height 0.26, standoff -0.04, extent -0.641,-4.147 -0.35,-3.852
3D body: height 0.26, standoff -0.04, extent -0.141,-4.147 0.15,-3.852
3D body: height 0.26, standoff -0.04, extent 0.359,-4.147 0.65,-3.852
3D body: height 0.26, standoff -0.04, extent 0.859,-4.147 1.15,-3.852
3D body: height 0.26, standoff -0.04, extent 1.359,-4.147 1.65,-3.852
3D body: height 0.26, standoff -0.04, extent 1.859,-4.147 2.15,-3.852
3D body: height 0.26, standoff -0.04, extent 2.359,-4.147 2.65,-3.852
3D body: height 0.26, standoff -0.04, extent 2.859,-4.147 3.15,-3.852
3D body: height 0.26, standoff -0.04, extent 3.359,-4.147 3.65,-3.852
3D body: height 0.26, standoff -0.04, extent 3.859,-4.147 4.15,-3.852
3D body: height 0.26, standoff -0.04, extent 4.359,-4.147 4.65,-3.852
3D body: height 0.26, standoff -0.04, extent -3.141,-3.647 -2.85,-3.352
3D body: height 0.26, standoff -0.04, extent -2.641,-3.647 -2.35,-3.352
3D body: height 0.26, standoff -0.04, extent -2.141,-3.647 -1.85,-3.352
3D body: height 0.26, standoff -0.04, extent -1.641,-3.647 -1.35,-3.352
3D body: height 0.26, standoff -0.04, extent -1.141,-3.647 -0.85,-3.352
3D body: height 0.26, standoff -0.04, extent -0.641,-3.647 -0.35,-3.352
3D body: height 0.26, standoff -0.04, extent -0.141,-3.647 0.15,-3.352
3D body: height 0.26, standoff -0.04, extent 0.359,-3.647 0.65,-3.352
3D body: height 0.26, standoff -0.04, extent 0.859,-3.647 1.15,-3.352
3D body: height 0.26, standoff -0.04, extent 1.359,-3.647 1.65,-3.352
3D body: height 0.26, standoff -0.04, extent 1.859,-3.647 2.15,-3.352
3D body: height 0.26, standoff -0.04, extent 2.359,-3.647 2.65,-3.352
3D body: height 0.26, standoff -0.04, extent 2.859,-3.647 3.15,-3.352
3D body: height 0.26, standoff -0.04, extent 3.359,-3.647 3.65,-3.352
3D body: height 0.26, standoff -0.04, extent 3.859,-3.647 4.15,-3.352
3D body: height 0.26, standoff -0.04, extent 4.359,-3.647 4.65,-3.352
3D body: height 0.26, standoff -0.04, extent 4.352,-3.141 4.647,-2.85
3D body: height 0.26, standoff -0.04, extent 4.352,-2.641 4.647,-2.35
3D body: height 0.26, standoff -0.04, extent 4.352,-1.641 4.647,-1.35
3D body: height 0.26, standoff -0.04, extent 4.352,-1.141 4.647,-0.85
3D body: height 0.26, standoff -0.04, extent 4.352,-0.141 4.647,0.15
3D body: height 0.26, standoff -0.04, extent 4.352,0.359 4.647,0.65
3D body: height 0.26, standoff -0.04, extent 4.352,1.359 4.647,1.65
3D body: height 0.26, standoff -0.04, extent 4.352,1.859 4.647,2.15
3D body: height 0.26, standoff -0.04, extent 4.352,2.859 4.647,3.15
3D body: height 0.26, standoff -0.04, extent 3.852,-3.141 4.147,-2.85
3D body: height 0.26, standoff -0.04, extent 3.852,-2.641 4.147,-2.35
3D body: height 0.26, standoff -0.04, extent 3.852,-2.141 4.147,-1.85
3D body: height 0.26, standoff -0.04, extent 3.852,-1.641 4.147,-1.35
3D body: height 0.26, standoff -0.04, extent 3.852,-1.141 4.147,-0.85
3D body: height 0.26, standoff -0.04, extent 3.852,-0.641 4.147,-0.35
3D body: height 0.26, standoff -0.04, extent 3.852,-0.141 4.147,0.15
3D body: height 0.26, standoff -0.04, extent 3.852,0.359 4.147,0.65
3D body: height 0.26, standoff -0.04, extent 3.852,0.859 4.147,1.15
3D body: height 0.26, standoff -0.04, extent 3.852,1.359 4.147,1.65
3D body: height 0.26, standoff -0.04, extent 3.852,1.859 4.147,2.15
3D body: height 0.26, standoff -0.04, extent 3.852,2.359 4.147,2.65
3D body: height 0.26, standoff -0.04, extent 3.852,2.859 4.147,3.15
3D body: height 0.26, standoff -0.04, extent 3.352,-3.141 3.647,-2.85
3D body: height 0.26, standoff -0.04, extent 3.352,-2.641 3.647,-2.35
3D body: height 0.26, standoff -0.04, extent 3.352,-2.141 3.647,-1.85
3D body: height 0.26, standoff -0.04, extent 3.352,-1.641 3.647,-1.35
3D body: height 0.26, standoff -0.04, extent 3.352,-1.141 3.647,-0.85
3D body: height 0.26, standoff -0.04, extent 3.352,-0.641 3.647,-0.35
3D body: height 0.26, standoff -0.04, extent 3.352,-0.141 3.647,0.15
3D body: height 0.26, standoff -0.04, extent 3.352,0.359 3.647,0.65
3D body: height 0.26, standoff -0.04, extent 3.352,0.859 3.647,1.15
3D body: height 0.26, standoff -0.04, extent 3.352,1.359 3.647,1.65
3D body: height 0.26, standoff -0.04, extent 3.352,1.859 3.647,2.15
3D body: height 0.26, standoff -0.04, extent 3.352,2.359 3.647,2.65
3D body: height 0.26, standoff -0.04, extent 3.352,2.859 3.647,3.15
3D body: height 0.26, standoff -0.04, extent -3.648,-4.641 -3.353,-4.35
3D body: height 0.26, standoff -0.04, extent -3.648,-4.141 -3.353,-3.85
3D body: height 0.26, standoff -0.04, extent -3.648,-3.641 -3.353,-3.35
3D body: height 0.26, standoff -0.04, extent -3.648,-3.141 -3.353,-2.85
3D body: height 0.26, standoff -0.04, extent -3.648,-2.641 -3.353,-2.35
3D body: height 0.26, standoff -0.04, extent -3.648,-2.141 -3.353,-1.85
3D body: height 0.26, standoff -0.04, extent -3.648,-1.641 -3.353,-1.35
3D body: height 0.26, standoff -0.04, extent -3.648,-1.141 -3.353,-0.85
3D body: height 0.26, standoff -0.04, extent -3.648,-0.641 -3.353,-0.35
3D body: height 0.26, standoff -0.04, extent -3.648,-0.141 -3.353,0.15
3D body: height 0.26, standoff -0.04, extent -3.648,0.359 -3.353,0.65
3D body: height 0.26, standoff -0.04, extent -3.648,0.859 -3.353,1.15
3D body: height 0.26, standoff -0.04, extent -3.648,1.359 -3.353,1.65
3D body: height 0.26, standoff -0.04, extent -3.648,1.859 -3.353,2.15
3D body: height 0.26, standoff -0.04, extent -3.648,2.359 -3.353,2.65
3D body: height 0.26, standoff -0.04, extent -3.648,2.859 -3.353,3.15
3D body: height 0.26, standoff -0.04, extent -4.148,-4.641 -3.853,-4.35
3D body: height 0.26, standoff -0.04, extent -4.148,-4.141 -3.853,-3.85
3D body: height 0.26, standoff -0.04, extent -4.148,-3.641 -3.853,-3.35
3D body: height 0.26, standoff -0.04, extent -4.148,-3.141 -3.853,-2.85
3D body: height 0.26, standoff -0.04, extent -4.148,-2.641 -3.853,-2.35
3D body: height 0.26, standoff -0.04, extent -4.148,-2.141 -3.853,-1.85
3D body: height 0.26, standoff -0.04, extent -4.148,-1.641 -3.853,-1.35
3D body: height 0.26, standoff -0.04, extent -4.148,-1.141 -3.853,-0.85
3D body: height 0.26, standoff -0.04, extent -4.148,-0.641 -3.853,-0.35
3D body: height 0.26, standoff -0.04, extent -4.148,-0.141 -3.853,0.15
3D body: height 0.26, standoff -0.04, extent -4.148,0.359 -3.853,0.65
3D body: height 0.26, standoff -0.04, extent -4.148,0.859 -3.853,1.15
3D body: height 0.26, standoff -0.04, extent -4.148,1.359 -3.853,1.65
3D body: height 0.26, standoff -0.04, extent -4.148,1.859 -3.853,2.15
3D body: height 0.26, standoff -0.04, extent -4.148,2.359 -3.853,2.65
3D body: height 0.26, standoff -0.04, extent -4.148,2.859 -3.853,3.15
3D body: height 0.26, standoff -0.04, extent -4.648,-4.641 -4.353,-4.35
3D body: height 0.26, standoff -0.04, extent -4.648,-4.141 -4.353,-3.85
3D body: height 0.26, standoff -0.04, extent -4.648,-3.641 -4.353,-3.35
3D body: height 0.26, standoff -0.04, extent -4.648,-3.141 -4.353,-2.85
3D body: height 0.26, standoff -0.04, extent -4.648,-2.141 -4.353,-1.85
3D body: height 0.26, standoff -0.04, extent -4.648,-1.641 -4.353,-1.35
3D body: height 0.26, standoff -0.04, extent -4.648,-0.641 -4.353,-0.35
3D body: height 0.26, standoff -0.04, extent -4.648,-0.141 -4.353,0.15
3D body: height 0.26, standoff -0.04, extent -4.648,0.859 -4.353,1.15
3D body: height 0.26, standoff -0.04, extent -4.648,1.359 -4.353,1.65
3D body: height 0.26, standoff -0.04, extent -4.648,2.359 -4.353,2.65
3D body: height 0.26, standoff -0.04, extent -4.648,2.859 -4.353,3.15
3D body: height 0.26, standoff -0.04, extent -4.641,3.353 -4.35,3.648
3D body: height 0.26, standoff -0.04, extent -4.141,3.353 -3.85,3.648
3D body: height 0.26, standoff -0.04, extent -3.641,3.353 -3.35,3.648
3D body: height 0.26, standoff -0.04, extent -3.141,3.353 -2.85,3.648
3D body: height 0.26, standoff -0.04, extent -2.641,3.353 -2.35,3.648
3D body: height 0.26, standoff -0.04, extent -2.141,3.353 -1.85,3.648
3D body: height 0.26, standoff -0.04, extent -1.641,3.353 -1.35,3.648
3D body: height 0.26, standoff -0.04, extent -1.141,3.353 -0.85,3.648
3D body: height 0.26, standoff -0.04, extent -0.641,3.353 -0.35,3.648
3D body: height 0.26, standoff -0.04, extent -0.141,3.353 0.15,3.648
3D body: height 0.26, standoff -0.04, extent 0.359,3.353 0.65,3.648
3D body: height 0.26, standoff -0.04, extent 0.859,3.353 1.15,3.648
3D body: height 0.26, standoff -0.04, extent 1.359,3.353 1.65,3.648
3D body: height 0.26, standoff -0.04, extent 1.859,3.353 2.15,3.648
3D body: height 0.26, standoff -0.04, extent 2.359,3.353 2.65,3.648
3D body: height 0.26, standoff -0.04, extent 2.859,3.353 3.15,3.648
3D body: height 0.26, standoff -0.04, extent 3.359,3.353 3.65,3.648
3D body: height 0.26, standoff -0.04, extent 3.859,3.353 4.15,3.648
3D body: height 0.26, standoff -0.04, extent 4.359,3.353 4.65,3.648
3D body: height 0.26, standoff -0.04, extent 4.359,3.852 4.65,4.148
3D body: height 0.26, standoff -0.04, extent 3.859,3.852 4.15,4.148
3D body: height 0.26, standoff -0.04, extent 3.359,3.852 3.65,4.148
3D body: height 0.26, standoff -0.04, extent 2.859,3.852 3.15,4.148
3D body: height 0.26, standoff -0.04, extent 2.359,3.852 2.65,4.148
3D body: height 0.26, standoff -0.04, extent 1.859,3.852 2.15,4.148
3D body: height 0.26, standoff -0.04, extent 1.359,3.852 1.65,4.148
3D body: height 0.26, standoff -0.04, extent 0.859,3.852 1.15,4.148
3D body: height 0.26, standoff -0.04, extent 0.359,3.852 0.65,4.148
3D body: height 0.26, standoff -0.04, extent -0.141,3.852 0.15,4.148
3D body: height 0.26, standoff -0.04, extent -0.641,3.852 -0.35,4.148
3D body: height 0.26, standoff -0.04, extent -1.141,3.852 -0.85,4.148
3D body: height 0.26, standoff -0.04, extent -1.641,3.852 -1.35,4.148
3D body: height 0.26, standoff -0.04, extent -2.141,3.852 -1.85,4.148
3D body: height 0.26, standoff -0.04, extent -2.641,3.852 -2.35,4.148
3D body: height 0.26, standoff -0.04, extent -3.141,3.852 -2.85,4.148
3D body: height 0.26, standoff -0.04, extent -3.641,3.852 -3.35,4.148
3D body: height 0.26, standoff -0.04, extent -4.141,3.852 -3.85,4.148
3D body: height 0.26, standoff -0.04, extent -4.641,3.852 -4.35,4.148
3D body: height 1.21, standoff 1.2, extent -4.798,4.201 -4.2,4.799
3D body: height 1.2, standoff 0.2, extent -5.075,-5.075 5.075,5.075
3D body: height 0.26, standoff -0.04, extent -4.641,4.353 -4.35,4.648
3D body: height 0.26, standoff -0.04, extent -4.141,4.353 -3.85,4.648
3D body: height 0.26, standoff -0.04, extent -3.641,4.353 -3.35,4.648
3D body: height 0.26, standoff -0.04, extent -3.141,4.353 -2.85,4.648
3D body: height 0.26, standoff -0.04, extent -2.141,4.353 -1.85,4.648
3D body: height 0.26, standoff -0.04, extent -1.641,4.353 -1.35,4.648
3D body: height 0.26, standoff -0.04, extent -0.641,4.353 -0.35,4.648
3D body: height 0.26, standoff -0.04, extent -0.141,4.353 0.15,4.648
3D body: height 0.26, standoff -0.04, extent 0.859,4.353 1.15,4.648
3D body: height 0.26, standoff -0.04, extent 1.359,4.353 1.65,4.648
3D body: height 0.26, standoff -0.04, extent 2.359,4.353 2.65,4.648
3D body: height 0.26, standoff -0.04, extent 2.859,4.353 3.15,4.648
3D body: height 0.26, standoff -0.04, extent 3.359,4.353 3.65,4.648
3D body: height 0.26, standoff -0.04, extent 3.859,4.353 4.15,4.648
3D body: height 0.26, standoff -0.04, extent 4.359,4.353 4.65,4.648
